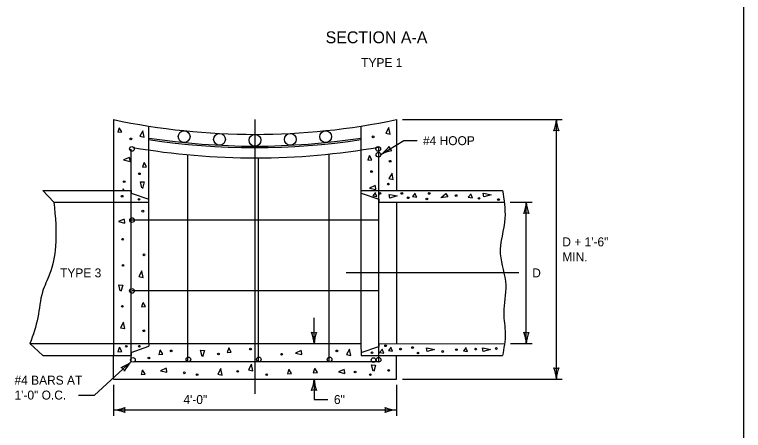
# Model space of a CAD drawing. Extents: x 49991.4 to 50021, y 49987.6 to 50011.4.
# Drawn here: x 50003.173 to 50008.067, y 49993.31 to 49996.102 of the extents above; entities that cross this region are included whole.
import ezdxf

# ---------------------------------------------------------------- set-up
doc = ezdxf.new("R2010")
doc.units = 0
for name, color, linetype in [('Level 1', 7, 'Continuous'), ('Level 2', 7, 'Continuous'), ('Level 3', 7, 'Continuous'), ('Level 4', 7, 'Continuous'), ('Level 5', 7, 'Continuous')]:
    doc.layers.add(name, color=color, linetype=linetype)

msp = doc.modelspace()

# ---------------------------------------------------------------- linework, layer by layer
at = {"layer": 'Level 1'}
for p, q in [((50008.0668, 49998.9992), (50008.0668, 49987.7988)), ((50003.8366, 49995.3966), (50003.8366, 49994.9216)), ((50005.7366, 49995.3966), (50005.7366, 49994.9216)), ((50004.0741, 49993.8924), (50004.0741, 49995.353)), ((50005.4992, 49993.8544), (50005.4992, 49995.353)), ((50003.9553, 49993.7737), (50003.9553, 49995.1972)), ((50005.6178, 49994.8424), (50005.6178, 49995.2167)), ((50004.3353, 49993.7737), (50004.3353, 49995.1608)), ((50005.2853, 49993.7737), (50005.2853, 49995.1655)), ((50004.8103, 49993.7737), (50004.8103, 49995.1394)), ((50003.8366, 49994.9216), (50003.8366, 49993.8133)), ((50005.4992, 49994.9216), (50006.4491, 49994.9216)), ((50005.4992, 49994.9025), (50005.6179, 49994.863)), ((50005.6179, 49994.863), (50005.6179, 49994.8424)), ((50005.6179, 49994.8424), (50006.4603, 49994.8424)), ((50005.6179, 49994.3859), (50005.6179, 49994.8424)), ((50003.9603, 49994.7237), (50005.6179, 49994.7237)), ((50005.6179, 49993.8949), (50005.6179, 49994.3859)), ((50003.962, 49994.2487), (50005.6179, 49994.2487)), ((50004.0741, 49993.8924), (50005.4992, 49993.8924)), ((50005.6178, 49993.7737), (50005.6178, 49993.8924)), ((50005.6179, 49993.894), (50005.6179, 49993.8734)), ((50005.6179, 49993.8924), (50006.4628, 49993.8922)), ((50005.6179, 49993.8924), (50005.6179, 49993.8734)), ((50005.4992, 49993.8323), (50005.6179, 49993.8734)), ((50005.4992, 49993.8529), (50005.4992, 49993.8133)), ((50003.8366, 49993.6549), (50003.8366, 49993.8133)), ((50005.4992, 49993.8133), (50006.4491, 49993.8133)), ((50005.7366, 49993.6549), (50005.7366, 49993.8133)), ((50003.9791, 49993.7737), (50005.6179, 49993.7737)), ((50003.8366, 49993.6549), (50005.7366, 49993.6549))]:
    msp.add_line(p, q, dxfattribs=at)
for points in [[(50003.8742, 49995.3383), (50003.866, 49995.3115), (50003.8928, 49995.3138), (50003.8762, 49995.3424)], [(50005.6869, 49995.3426), (50005.6665, 49995.3056), (50005.6951, 49995.2995), (50005.6869, 49995.3406)], [(50004.034, 49995.3222), (50004.0135, 49995.2852), (50004.0422, 49995.279), (50004.034, 49995.3201)], [(50005.5537, 49995.1519), (50005.5454, 49995.1251), (50005.5722, 49995.1274), (50005.5557, 49995.156)], [(50003.9439, 49995.1418), (50003.905, 49995.1254), (50003.948, 49995.1149), (50003.9459, 49995.1397)], [(50004.0401, 49995.1049), (50004.0319, 49995.0781), (50004.0587, 49995.0804), (50004.0422, 49995.109)], [(50005.7073, 49995.0375), (50005.6869, 49995.0005), (50005.7155, 49994.9944), (50005.7073, 49995.0354)], [(50004.0279, 49994.9389), (50004.0176, 49994.9799), (50004.0441, 49994.9778), (50004.0319, 49994.9349)], [(50005.5947, 49994.9534), (50005.5559, 49994.9369), (50005.5987, 49994.9265), (50005.5967, 49994.9513)], [(50003.9007, 49994.9267), (50003.8976, 49994.9167)], [(50003.9109, 49994.9167), (50003.9028, 49994.9308)], [(50005.5959, 49994.908), (50005.5776, 49994.8854), (50005.6062, 49994.8813), (50005.594, 49994.906)], [(50005.8631, 49994.903), (50005.8447, 49994.8803), (50005.8733, 49994.8763), (50005.8611, 49994.9009)], [(50006.3239, 49994.9028), (50006.3731, 49994.8925), (50006.3239, 49994.8782), (50006.3199, 49994.9028)], [(50005.6931, 49994.8945), (50005.7423, 49994.8844), (50005.6931, 49994.87), (50005.689, 49994.8945)], [(50006.0372, 49994.8742), (50006.0681, 49994.9009), (50006.0824, 49994.8782), (50006.0351, 49994.8721)], [(50006.2379, 49994.8989), (50006.2195, 49994.8762), (50006.248, 49994.8721), (50006.2359, 49994.8969)], [(50003.909, 49994.7286), (50003.8701, 49994.7123), (50003.9131, 49994.7019), (50003.911, 49994.7265)], [(50004.028, 49994.3806), (50004.0076, 49994.3436), (50004.036, 49994.3375), (50004.028, 49994.3786)], [(50003.8824, 49994.2473), (50003.8722, 49994.2882), (50003.8987, 49994.2861), (50003.8865, 49994.2432)], [(50004.0339, 49994.1654), (50004.0256, 49994.1386), (50004.0525, 49994.1409), (50004.036, 49994.1695)], [(50003.9049, 49994.0362), (50003.8845, 49993.9992), (50003.9131, 49993.9931), (50003.9049, 49994.0342)], [(50003.8751, 49993.8653), (50003.8668, 49993.8385), (50003.8936, 49993.8408), (50003.8771, 49993.8694)], [(50004.1487, 49993.8457), (50004.1405, 49993.8189), (50004.1674, 49993.8212), (50004.1508, 49993.8499)], [(50004.4314, 49993.8069), (50004.4211, 49993.8478), (50004.4477, 49993.8457), (50004.4354, 49993.8029)], [(50004.611, 49993.865), (50004.6013, 49993.8333), (50004.6282, 49993.8355), (50004.611, 49993.865)], [(50005.0969, 49993.8458), (50005.0581, 49993.8294), (50005.1011, 49993.8189), (50005.099, 49993.8438)], [(50005.4227, 49993.8562), (50005.4023, 49993.8192), (50005.4308, 49993.8131), (50005.4227, 49993.8542)], [(50005.6427, 49993.8564), (50005.6243, 49993.8337), (50005.6529, 49993.8297), (50005.6407, 49993.8544)], [(50005.7012, 49993.8684), (50005.6828, 49993.8457), (50005.7114, 49993.8417), (50005.6992, 49993.8664)], [(50005.943, 49993.8641), (50005.9922, 49993.8539), (50005.943, 49993.8396), (50005.939, 49993.8641)], [(50006.205, 49993.8664), (50006.1865, 49993.8438), (50006.2151, 49993.8396), (50006.203, 49993.8644)], [(50006.3198, 49993.8641), (50006.369, 49993.8539), (50006.3198, 49993.8396), (50006.3158, 49993.8641)], [(50004.7641, 49993.7539), (50004.7436, 49993.7169), (50004.7722, 49993.7107), (50004.7641, 49993.7518)], [(50005.5805, 49993.7086), (50005.5702, 49993.7494), (50005.5968, 49993.7474), (50005.5845, 49993.7045)], [(50004.0303, 49993.7132), (50004.022, 49993.6863), (50004.0488, 49993.6886), (50004.0323, 49993.7172)], [(50004.1915, 49993.727), (50004.1528, 49993.7107), (50004.1957, 49993.7002), (50004.1936, 49993.725)], [(50004.5583, 49993.725), (50004.5379, 49993.688), (50004.5664, 49993.6819), (50004.5583, 49993.7229)], [(50005.0129, 49993.7168), (50005.0048, 49993.69), (50005.0316, 49993.6923), (50005.015, 49993.7209)], [(50005.1871, 49993.7229), (50005.1789, 49993.6962), (50005.2058, 49993.6984), (50005.1892, 49993.727)], [(50005.3857, 49993.7189), (50005.3469, 49993.7025), (50005.3897, 49993.692), (50005.3877, 49993.7169)]]:
    msp.add_lwpolyline(points, dxfattribs=at)
for centre in [(50003.9542, 49995.2668), (50005.5804, 49995.2811), (50005.695, 49995.1172), (50005.5702, 49995.0475), (50004.0115, 49995.0332), (50003.909, 49994.9798), (50005.6828, 49994.9635), (50005.6255, 49994.9007), (50005.773, 49994.9007), (50005.9573, 49994.9007), (50003.8947, 49994.8823), (50004.0085, 49994.8612), (50005.8159, 49994.8721), (50005.941, 49994.8637), (50006.1376, 49994.8864), (50006.291, 49994.8678), (50006.4222, 49994.8596), (50004.0341, 49994.782), (50003.8989, 49994.5936), (50004.0423, 49994.4889), (50003.9009, 49994.4174), (50003.8968, 49994.1429), (50004.0402, 49993.979), (50003.9233, 49993.8748), (50004.0108, 49993.8749), (50005.6639, 49993.8784), (50004.2246, 49993.8437), (50004.5419, 49993.8233), (50004.7571, 49993.856), (50004.966, 49993.8213), (50005.3367, 49993.8437), (50005.5732, 49993.8314), (50005.7648, 49993.856), (50005.8447, 49993.8664), (50005.8815, 49993.8294), (50006.0474, 49993.8396), (50006.1396, 49993.8519), (50006.2686, 49993.856), (50006.4079, 49993.8601), (50004.075, 49993.796), (50004.3127, 49993.6964), (50004.3987, 49993.6841), (50004.6711, 49993.7066), (50004.8656, 49993.6841), (50005.4595, 49993.7025), (50005.5619, 49993.6841), (50005.6849, 49993.7127)]:
    msp.add_circle(centre, 0.00579, dxfattribs=at)
for major_axis, start_param, end_param in [((0, -4.6095), 6.075601, 6.49077), ((0, -4.6985), 6.130631, 6.435739), ((0, -4.6886), 6.13064, 6.435748), ((0, -4.7678), 6.110622, 6.458424)]:
    msp.add_ellipse((50004.7866, 49999.9071), major_axis=major_axis, ratio=0.99996, start_param=start_param, end_param=end_param, dxfattribs=at)
for centre, major_axis in [((50004.3116, 49995.2822), (0, 0.0396)), ((50004.5491, 49995.2641), (0, 0.0396)), ((50004.7866, 49995.2581), (0, 0.0396)), ((50005.0241, 49995.2641), (0, 0.0396)), ((50005.2616, 49995.2822), (0, 0.0396)), ((50003.9606, 49995.1995), (0, 0.0156)), ((50005.6146, 49995.2), (0, 0.0156)), ((50005.6162, 49995.1609), (0, 0.0156)), ((50003.9619, 49994.7223), (0, 0.0156)), ((50003.9611, 49994.2466), (0, 0.0156)), ((50003.9672, 49993.7837), (0, 0.0156)), ((50004.3399, 49993.7866), (0, 0.0156)), ((50004.8129, 49993.7866), (0, 0.0156)), ((50005.2881, 49993.7866), (0, 0.0156)), ((50005.5829, 49993.7825), (0, 0.0156)), ((50005.6171, 49993.7841), (0, 0.0156))]:
    msp.add_ellipse(centre, major_axis=major_axis, ratio=0.99996, dxfattribs=at)
msp.add_spline([(50006.4491, 49994.9216), (50006.4651, 49994.7348), (50006.4345, 49994.495), (50006.4712, 49994.2861), (50006.457, 49994.0998), (50006.4672, 49993.9585), (50006.4491, 49993.8133)], degree=3, dxfattribs=at)
at = {"layer": 'Level 3'}
for p, q in [((50005.7766, 49995.3966), (50006.8508, 49995.3966)), ((50006.8108, 49993.6549), (50006.8108, 49995.3966)), ((50005.6318, 49995.1615), (50005.7857, 49995.2552)), ((50005.7857, 49995.2552), (50005.8753, 49995.2552)), ((50006.5003, 49994.8424), (50006.6488, 49994.8424)), ((50006.6088, 49993.8924), (50006.6088, 49994.8424)), ((50005.184, 49993.8924), (50005.184, 49994.0658)), ((50006.5028, 49993.8924), (50006.6488, 49993.8924)), ((50003.7094, 49993.5473), (50003.9568, 49993.7721)), ((50005.184, 49993.6549), (50005.184, 49993.5174)), ((50005.7766, 49993.6549), (50006.8508, 49993.6549)), ((50003.8366, 49993.6149), (50003.8366, 49993.4072)), ((50005.7366, 49993.6149), (50005.7366, 49993.4072)), ((50003.6029, 49993.5473), (50003.7094, 49993.5473)), ((50005.184, 49993.5174), (50005.2772, 49993.5174)), ((50003.8366, 49993.4472), (50005.7366, 49993.4472))]:
    msp.add_line(p, q, dxfattribs=at)
for centre, radius, start, end in [((50005.5009, 49995.3542), 0.233, 304.168, 323.4179), ((50005.7413, 49995.2281), 0.0548, 193.4795, 229.2019), ((50005.7395, 49994.967), 0.2223, 98.7967, 118.9802), ((50003.8142, 49993.9427), 0.2223, 289.7159, 309.8994), ((50003.8619, 49993.6859), 0.0548, 24.3987, 60.121), ((50004.1218, 49993.6076), 0.233, 135.0872, 154.337)]:
    msp.add_arc(centre, radius, start, end, dxfattribs=at)
for centre, major_axis, start_param, end_param in [((50006.5887, 49995.4058), (0, -0.2223), 1.177329, 1.529598), ((50007.0435, 49995.4081), (0, -0.233), 4.761735, 5.097708), ((50006.8108, 49995.2684), (0, 0.0548), 5.971449, 6.594922), ((50006.3867, 49994.8516), (0, -0.2223), 1.177329, 1.529598), ((50006.8415, 49994.8539), (0, -0.233), 4.761735, 5.097708), ((50006.6088, 49994.7142), (0, 0.0548), 5.971449, 6.594922), ((50005.184, 49994.0206), (0, -0.0548), 5.971449, 6.594922), ((50004.9513, 49993.8809), (0, 0.233), 4.761735, 5.097708), ((50005.4061, 49993.8832), (0, 0.2223), 1.177329, 1.529598), ((50006.6088, 49994.0206), (0, -0.0548), 5.971449, 6.594922), ((50006.3761, 49993.8809), (0, 0.233), 4.761735, 5.097708), ((50006.8309, 49993.8832), (0, 0.2223), 1.177329, 1.529598), ((50006.8108, 49993.7831), (0, -0.0548), 5.971449, 6.594922), ((50006.5781, 49993.6434), (0, 0.233), 4.761735, 5.097708), ((50007.0329, 49993.6457), (0, 0.2223), 1.177329, 1.529598), ((50004.9619, 49993.6641), (0, -0.2223), 1.177329, 1.529598), ((50005.4167, 49993.6664), (0, -0.233), 4.761735, 5.097708), ((50005.184, 49993.5267), (0, 0.0548), 5.971449, 6.594922), ((50003.8251, 49993.6799), (0, -0.233), 0.049346, 0.385319), ((50003.8274, 49993.2251), (0, 0.2223), 5.889718, 6.241987), ((50003.9648, 49993.4472), (0, 0.0548), 1.25906, 1.882533), ((50005.7458, 49993.6693), (0, -0.2223), 5.889718, 6.241987), ((50005.6084, 49993.4472), (0, -0.0548), 1.25906, 1.882533), ((50005.7481, 49993.2145), (0, 0.233), 0.049346, 0.385319)]:
    msp.add_ellipse(centre, major_axis=major_axis, ratio=0.99996, start_param=start_param, end_param=end_param, dxfattribs=at)
at = {"layer": 'Level 4'}
for p, q in [((50003.3617, 49994.9216), (50003.9554, 49994.9216)), ((50003.4374, 49994.8424), (50003.3617, 49994.9216)), ((50003.9554, 49994.9216), (50003.9554, 49994.9026)), ((50003.9554, 49994.9026), (50004.0741, 49994.8614)), ((50003.4374, 49994.8424), (50004.0741, 49994.8424)), ((50005.7366, 49994.8424), (50005.7366, 49993.8924)), ((50003.2763, 49993.8924), (50004.0741, 49993.8924)), ((50003.3617, 49993.8133), (50003.2763, 49993.8924)), ((50003.9554, 49993.8339), (50004.0741, 49993.875)), ((50004.0741, 49993.8924), (50004.0741, 49993.875)), ((50003.9554, 49993.8339), (50003.9554, 49993.8133)), ((50003.3617, 49993.8133), (50003.9554, 49993.8133))]:
    msp.add_line(p, q, dxfattribs=at)
msp.add_spline([(50003.4374, 49994.8424), (50003.4477, 49994.5444), (50003.4082, 49994.3595), (50003.3607, 49994.2408), (50003.3291, 49994.0691), (50003.2763, 49993.8924)], degree=3, dxfattribs=at)
at = {"layer": 'Level 5'}
for p, q in [((50004.7865, 49995.3976), (50004.7866, 49993.5549)), ((50006.559, 49994.3671), (50005.3992, 49994.3671))]:
    msp.add_line(p, q, dxfattribs=at)

# ---------------------------------------------------------------- texts
at = {"layer": 'Level 2'}
for s, height, p in [('SECTION A-A', 0.08, (50005.2614, 49995.9091)), ('TYPE 1', 0.06, (50005.5005, 49995.7491)), ('#4 HOOP', 0.06, (50005.9153, 49995.2252)), ('D + 1\'-6"', 0.06, (50006.8508, 49994.5458)), ('MIN.', 0.06, (50006.8508, 49994.4457)), ('TYPE 3', 0.06, (50003.4787, 49994.3375)), ('D', 0.06, (50006.6488, 49994.3374)), ('#4 BARS AT', 0.06, (50003.1726, 49993.6173)), ('1\'-0" O.C.', 0.06, (50003.1726, 49993.5173)), ('4\'-0"', 0.06, (50004.3067, 49993.4872)), ('6"', 0.06, (50005.3172, 49993.4874))]:
    msp.add_text(s, height=height, dxfattribs=at).set_placement(p)

doc.saveas('drawing.dxf')
